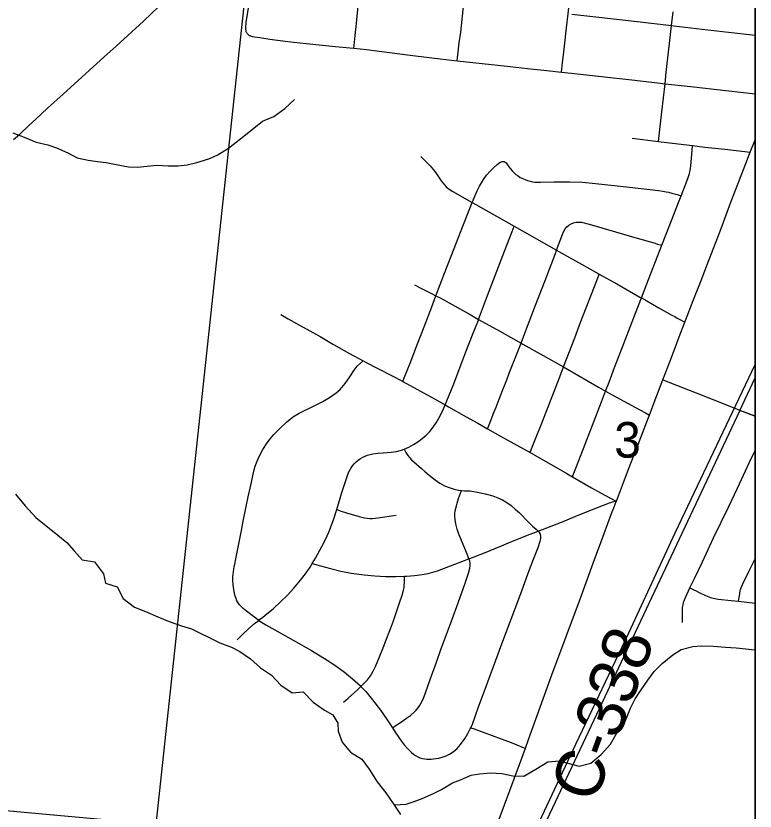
# Model space of a CAD drawing. Extents: x 0 to 1134, y 0 to 440.
# Drawn here: x 512.92 to 539, y 176.75 to 204.78 of the extents above; entities that cross this region are included whole.
import ezdxf

# ---------------------------------------------------------------- set-up
doc = ezdxf.new("R2010")
doc.units = 0
for name, color, linetype in [('Default', 7, 'Continuous'), ('GM_X_City_Street', 7, 'Continuous'), ('GM_X_County_Road', 7, 'Continuous'), ('GM_X_County_Road_Text', 7, 'Continuous'), ('GM_X_Minor_River', 7, 'Continuous'), ('GM_X_Rail_Line', 7, 'Continuous'), ('GM_X_Section', 7, 'Continuous'), ('GM_X_Section_Text', 7, 'Continuous'), ('GM_X_Township_Road', 7, 'Continuous'), ('GM_X_Unincorporated', 7, 'Continuous'), ('SH_Cut_Line', 7, 'Continuous'), ('SH_Text', 7, 'Continuous')]:
    doc.layers.add(name, color=color, linetype=linetype)

msp = doc.modelspace()

# ---------------------------------------------------------------- linework, layer by layer
at = {"layer": 'Default'}
msp.add_lwpolyline([(539, 174.139), (539, 205.4), (521.182, 207.228), (517.859, 176.283)], close=True, dxfattribs=at)
at = {"layer": 'GM_X_City_Street'}
for points in [[(521.083, 204.164), (521.072, 204.183), (521.062, 204.199), (521.051, 204.227), (521.042, 204.259), (521.037, 204.317), (521.036, 204.359), (521.05, 204.559), (521.091, 204.838), (521.19, 205.48), (521.245, 205.898), (521.274, 206.122), (521.291, 206.409), (521.321, 206.883), (521.352, 207.438), (521.393, 207.998), (521.403, 208.129), (521.401, 208.151), (521.398, 208.175), (521.391, 208.194), (521.379, 208.222), (521.333, 208.322)], [(532.166, 202.799), (532.18, 202.911), (532.21, 203.141), (532.233, 203.319), (532.277, 203.722), (532.347, 204.361), (532.404, 204.859), (532.454, 205.294), (532.528, 206.019), (532.576, 206.781), (532.617, 207.263), (532.654, 207.688), (532.685, 208.057), (532.724, 208.449)], [(524.844, 203.641), (524.855, 203.743), (524.892, 204.097), (524.926, 204.413), (524.949, 204.641), (524.976, 204.891), (525.024, 205.352), (525.06, 205.689), (525.091, 205.99), (525.14, 206.457), (525.204, 206.924), (525.257, 207.297), (525.309, 207.765), (525.328, 207.94)], [(528.49, 203.205), (528.562, 203.84), (528.614, 204.211), (528.721, 205.225), (528.728, 205.275), (528.746, 205.41), (528.766, 205.503), (528.825, 205.682), (528.863, 205.769), (528.996, 206.013), (529.034, 206.095), (529.064, 206.179), (529.088, 206.267), (529.106, 206.355), (529.127, 206.545), (529.145, 206.737), (529.164, 206.912), (529.187, 207.139), (529.218, 207.439), (529.233, 207.581)], [(535.595, 200.36), (535.619, 200.569), (535.715, 201.403), (535.822, 202.393), (535.866, 202.795), (535.985, 203.815), (536.054, 204.447), (536.107, 204.929)], [(532.54, 204.843), (533.276, 204.764), (534.842, 204.585), (536.054, 204.447), (536.132, 204.438), (537.333, 204.298), (539, 204.108)], [(521.083, 204.164), (521.102, 204.143), (521.128, 204.118), (521.156, 204.098), (521.176, 204.089), (521.195, 204.082), (521.261, 204.063), (521.341, 204.046), (521.531, 204.017), (521.887, 203.964), (522.522, 203.885), (523.166, 203.808), (524.199, 203.705), (524.708, 203.655), (524.844, 203.641), (525.297, 203.594), (526.732, 203.416), (527.593, 203.31), (528.087, 203.249), (528.49, 203.205), (529.046, 203.143), (530.248, 203.008), (531.081, 202.916), (531.544, 202.867), (532.166, 202.799), (532.738, 202.737), (533.58, 202.643), (534.647, 202.525), (535.556, 202.424), (535.822, 202.393), (536.729, 202.29), (537.557, 202.196), (539, 202.032)], [(534.663, 200.474), (535.595, 200.36), (535.887, 200.325), (536.795, 200.214), (537.222, 200.162), (537.927, 200.081), (538.637, 200), (538.829, 199.978)], [(532.556, 188.537), (532.607, 188.664), (532.676, 188.837), (532.945, 189.531), (533.577, 191.18), (533.725, 191.558), (533.847, 191.873), (534.044, 192.394), (534.306, 193.08), (534.776, 194.305), (534.987, 194.839), (535.186, 195.341), (535.714, 196.698), (535.995, 197.42), (536.295, 198.202), (536.396, 198.442), (536.537, 198.8), (536.631, 199.054), (536.683, 199.229), (536.72, 199.409), (536.731, 199.499), (536.753, 199.766), (536.779, 200.039), (536.795, 200.214)], [(526.57, 191.901), (526.62, 192.026), (526.827, 192.537), (527.096, 193.222), (527.329, 193.827), (527.593, 194.522), (527.742, 194.913), (528.048, 195.717), (528.282, 196.31), (528.712, 197.434), (529.018, 198.206), (529.088, 198.37), (529.195, 198.622), (529.278, 198.785), (529.418, 199.018), (529.525, 199.164), (529.644, 199.301), (529.773, 199.43), (529.884, 199.529), (529.96, 199.591), (530.005, 199.623), (530.044, 199.645), (530.083, 199.654)], [(527.203, 199.824), (527.456, 199.582), (527.538, 199.499), (527.657, 199.356), (527.714, 199.281), (527.921, 198.969), (528.039, 198.824), (528.105, 198.758), (528.176, 198.698), (528.332, 198.594), (529.018, 198.206), (529.146, 198.133), (529.881, 197.722), (530.501, 197.371), (531.999, 196.523), (532.079, 196.478), (533.464, 195.697), (533.504, 195.674), (534.118, 195.333), (534.93, 194.871), (534.987, 194.839), (535.177, 194.734), (535.58, 194.499), (536.062, 194.236), (536.164, 194.181), (536.255, 194.132), (536.346, 194.082), (536.525, 193.984)], [(530.083, 199.654), (530.114, 199.653), (530.15, 199.646), (530.18, 199.632), (530.214, 199.6), (530.267, 199.529), (530.314, 199.467), (530.43, 199.322), (530.495, 199.256), (530.565, 199.195), (530.639, 199.14), (530.718, 199.092), (530.885, 199.011), (530.973, 198.98), (531.062, 198.956), (531.153, 198.939), (531.245, 198.928), (531.431, 198.923), (531.894, 198.936), (532.45, 198.94), (532.913, 198.92), (533.375, 198.879), (534.573, 198.745), (535.587, 198.63), (535.744, 198.609), (535.861, 198.585), (535.946, 198.567), (536.057, 198.539), (536.246, 198.485), (536.396, 198.442)], [(528.067, 191.071), (528.125, 191.214), (528.369, 191.815), (528.593, 192.415), (528.688, 192.661), (528.795, 192.94), (529.034, 193.543), (529.238, 194.061), (529.247, 194.084), (529.564, 194.93), (530.162, 196.493), (530.428, 197.182), (530.501, 197.371)], [(529.564, 190.231), (529.616, 190.364), (529.788, 190.806), (529.861, 190.992), (529.969, 191.27), (530.089, 191.575), (530.238, 191.957), (530.328, 192.189), (530.743, 193.252), (530.803, 193.407), (531.258, 194.588), (531.589, 195.458), (531.957, 196.413), (531.999, 196.523), (532.22, 197.111), (532.258, 197.196), (532.303, 197.277), (532.361, 197.349), (532.432, 197.409), (532.512, 197.457), (532.598, 197.493), (532.689, 197.512), (532.782, 197.518), (532.875, 197.509), (533.145, 197.437), (533.592, 197.308), (534.757, 196.975), (535.473, 196.767), (535.562, 196.741), (535.714, 196.698)], [(531.061, 189.387), (531.115, 189.522), (531.304, 189.991), (531.427, 190.309), (531.555, 190.64), (531.695, 191.002), (531.859, 191.422), (532.106, 192.06), (532.24, 192.408), (532.637, 193.434), (532.834, 193.955), (533.44, 195.51), (533.504, 195.674)], [(526.984, 195.307), (527.227, 195.172), (527.558, 195.006), (527.742, 194.913), (527.889, 194.839), (528.943, 194.253), (529.247, 194.084), (529.999, 193.664), (530.743, 193.252), (530.812, 193.213), (532.24, 192.408), (532.38, 192.329), (533.479, 191.697), (533.725, 191.558), (533.963, 191.423), (534.782, 190.976), (535.129, 190.786), (535.27, 190.709)], [(536.437, 183.395), (536.437, 183.579), (536.437, 183.665), (536.436, 183.751), (536.438, 183.838), (536.444, 183.928), (536.457, 184.02), (536.478, 184.11), (536.505, 184.199), (536.539, 184.286), (536.701, 184.627), (536.857, 184.956), (537.142, 185.54), (537.531, 186.381), (538.061, 187.465), (538.376, 188.132), (538.808, 189.054), (539, 189.458)], [(538.415, 184.146), (538.446, 184.335), (538.475, 184.51), (538.49, 184.566), (538.507, 184.617), (538.53, 184.678), (538.577, 184.781), (538.776, 185.198), (539, 185.645)], [(536.701, 184.627), (536.842, 184.556), (536.923, 184.516), (537.005, 184.473), (537.254, 184.349), (537.427, 184.282), (537.516, 184.256), (537.697, 184.221), (538.157, 184.176), (538.415, 184.146), (539, 184.08)]]:
    msp.add_lwpolyline(points, dxfattribs=at)
at = {"layer": 'GM_X_County_Road'}
for p, q in [((538.829, 199.978), (539, 200.417)), ((538.546, 190.854), (539, 190.677)), ((534.017, 187.443), (534.052, 187.53))]:
    msp.add_line(p, q, dxfattribs=at)
for points in [[(512.836, 200.424), (513.046, 200.607), (513.381, 200.924), (513.626, 201.149), (514.039, 201.527), (514.595, 202.025), (516.043, 203.341), (516.459, 203.715), (517.426, 204.595), (517.965, 205.112), (518.509, 205.624), (518.95, 206.036)], [(536.525, 193.984), (536.55, 194.05), (536.82, 194.752), (537.093, 195.46), (537.356, 196.136), (537.626, 196.828), (537.804, 197.287), (538.148, 198.221), (538.673, 199.579), (538.829, 199.978)], [(535.747, 191.951), (535.987, 192.594), (536.154, 193.023), (536.326, 193.467), (536.525, 193.984)], [(535.27, 190.709), (535.478, 191.251), (535.747, 191.951)], [(535.747, 191.951), (536.92, 191.498), (538.047, 191.049), (538.546, 190.854)], [(534.106, 187.671), (534.433, 188.526), (534.562, 188.861), (534.702, 189.227), (534.838, 189.581), (534.967, 189.916), (535.237, 190.621), (535.27, 190.709)], [(534.052, 187.53), (534.079, 187.601), (534.106, 187.671)], [(530.895, 178.971), (531.003, 179.27), (531.421, 180.409), (531.835, 181.55), (532.84, 184.262), (533.288, 185.49), (533.678, 186.539), (533.935, 187.241), (534.017, 187.443)], [(529.505, 175.252), (529.739, 175.858), (529.974, 176.467), (530.685, 178.393), (530.895, 178.971)]]:
    msp.add_lwpolyline(points, dxfattribs=at)
at = {"layer": 'GM_X_Minor_River'}
for points in [[(512.814, 200.664), (513.221, 200.514), (513.64, 200.328), (514.048, 200.234), (514.353, 200.13), (514.76, 199.956), (515.088, 199.783), (515.473, 199.701), (515.802, 199.653), (516.108, 199.616), (516.46, 199.545), (516.89, 199.463), (517.208, 199.449), (517.549, 199.492), (517.89, 199.524), (518.298, 199.498), (518.65, 199.495), (518.968, 199.538), (519.309, 199.615), (519.73, 199.749), (520.026, 199.872), (520.425, 200.119), (520.859, 200.457), (521.258, 200.784), (521.624, 201.077), (522.022, 201.233), (522.41, 201.515), (522.753, 201.842)], [(512.911, 187.924), (513.249, 187.512), (513.631, 187.1), (514.398, 186.48), (514.726, 186.216), (514.984, 185.93), (515.266, 185.609), (515.697, 185.538), (516.011, 185.115), (516.088, 184.784), (516.496, 184.656), (516.708, 184.245), (517.103, 183.935), (517.499, 183.784), (517.929, 183.599), (518.336, 183.437), (518.767, 183.286), (519.117, 183.17), (519.423, 183.019), (519.739, 182.869), (520.112, 182.685), (520.531, 182.534), (520.825, 182.372), (521.198, 182.119), (521.547, 181.798), (521.942, 181.545), (522.269, 181.19), (522.664, 180.925), (523.062, 180.957), (523.411, 180.59), (523.806, 180.303), (524.1, 180.141), (524.279, 179.856), (524.288, 179.571), (524.433, 179.183), (524.725, 178.829), (525.121, 178.587), (525.39, 178.232), (525.671, 177.787), (525.974, 177.398), (526.232, 177.02), (526.491, 176.632)], [(526.267, 176.968), (526.686, 176.994), (526.971, 177.083), (527.255, 177.195), (527.654, 177.374), (527.938, 177.508), (528.326, 177.744), (528.611, 177.856), (528.986, 178.012), (529.282, 178.067), (529.668, 178.098), (530.065, 178.072), (530.45, 177.99), (530.847, 177.976), (531.269, 178.223), (531.691, 178.492), (532.1, 178.524), (532.394, 178.442), (532.791, 178.336), (533.2, 178.436), (533.565, 178.74), (533.897, 179.113), (534.15, 179.543), (534.437, 179.973), (534.61, 180.381), (534.772, 180.71), (534.978, 181.027), (535.219, 181.366), (535.437, 181.672), (535.723, 181.954), (536.1, 182.258), (536.396, 182.449), (536.805, 182.549), (537.101, 182.581), (537.532, 182.566), (537.952, 182.529), (538.326, 182.503), (538.677, 182.466), (538.995, 182.441), (539, 182.44)]]:
    msp.add_lwpolyline(points, dxfattribs=at)
at = {"layer": 'GM_X_Rail_Line'}
for p, q in [((538.46, 190.872), (539, 192.029)), ((539, 190.675), (538.46, 190.872))]:
    msp.add_line(p, q, dxfattribs=at)
for points in [[(523.793, 152.748), (524.72, 156.111), (526.82, 163.501), (529.132, 171.547), (530.926, 175.384), (532.671, 179.109), (534.549, 183.03), (536.181, 186.563), (539, 192.493)], [(538.46, 190.872), (531.264, 175.625), (529.455, 171.744), (523.761, 151.987), (521.638, 146.912), (519.773, 143.896), (517.683, 141.431), (515.36, 138.979), (514.776, 138.349), (513.736, 135.72), (513.018, 133.756), (510.064, 126.441), (504.279, 111.389), (503.424, 109.358), (496.783, 96.163), (485.546, 73.661), (478.157, 58.904), (470.789, 44.152), (463.212, 28.991)]]:
    msp.add_lwpolyline(points, dxfattribs=at)
at = {"layer": 'GM_X_Section'}
msp.add_lwpolyline([(490.882, 209.496), (521.182, 207.228), (517.859, 176.283), (488.076, 178.987)], close=True, dxfattribs=at)
at = {"layer": 'GM_X_Township_Road'}
for points in [[(522.267, 194.257), (522.524, 194.109), (522.924, 193.878), (523.656, 193.483), (524.133, 193.204), (524.695, 192.885), (525.175, 192.624)], [(521.488, 183.475), (521.462, 183.493), (521.385, 183.551), (521.305, 183.611), (521.061, 183.799), (520.945, 183.897), (520.874, 183.959), (520.812, 184.027), (520.762, 184.098), (520.721, 184.164), (520.69, 184.242), (520.659, 184.329), (520.636, 184.439), (520.611, 184.567), (520.593, 184.726), (520.577, 184.887), (520.579, 185.004), (520.584, 185.096), (520.595, 185.189), (520.622, 185.372), (520.641, 185.46), (520.677, 185.643), (520.879, 186.647), (520.945, 186.973), (521.037, 187.431), (521.118, 187.832), (521.217, 188.286), (521.255, 188.466), (521.316, 188.735), (521.367, 188.914), (521.431, 189.088), (521.507, 189.256), (521.64, 189.501), (521.79, 189.737), (521.901, 189.887), (522.02, 190.031), (522.22, 190.232), (522.466, 190.465), (522.594, 190.569), (522.715, 190.657), (522.777, 190.697), (522.914, 190.775), (523.417, 191.02), (523.75, 191.189), (523.99, 191.333), (524.218, 191.496), (524.36, 191.617), (524.425, 191.683), (524.543, 191.828), (524.698, 192.061), (524.851, 192.296), (524.968, 192.44), (525.175, 192.624)], [(525.175, 192.624), (525.579, 192.409), (526.317, 192.04), (526.57, 191.901)], [(526.57, 191.901), (527.695, 191.28), (528.067, 191.071)], [(526.615, 189.511), (526.782, 189.584), (526.946, 189.675), (527.104, 189.774), (527.258, 189.881), (527.399, 190.001), (527.529, 190.136), (527.645, 190.281), (527.747, 190.438), (527.885, 190.686), (528.012, 190.934), (528.067, 191.071)], [(528.067, 191.071), (528.179, 191.008), (528.813, 190.651), (529.214, 190.431), (529.564, 190.231)], [(529.564, 190.231), (530.017, 189.971), (531.061, 189.387)], [(524.242, 187.378), (524.419, 187.98), (524.536, 188.335), (524.618, 188.587), (524.66, 188.686), (524.699, 188.77), (524.746, 188.851), (524.8, 188.927), (524.861, 188.998), (524.928, 189.063), (525, 189.122), (525.076, 189.176), (525.157, 189.223), (525.241, 189.263), (525.328, 189.297), (525.418, 189.325), (525.509, 189.345), (525.694, 189.366), (525.881, 189.382), (526.16, 189.407), (526.345, 189.43), (526.436, 189.448), (526.526, 189.472), (526.615, 189.511)], [(526.615, 189.511), (526.675, 189.395), (526.744, 189.287), (526.807, 189.214), (526.88, 189.136), (527.23, 188.827), (527.364, 188.714), (527.506, 188.596), (527.717, 188.429), (527.877, 188.311), (527.956, 188.263), (528.038, 188.221), (528.21, 188.154), (528.387, 188.098), (528.534, 188.064), (528.64, 188.049)], [(531.061, 189.387), (531.228, 189.293), (532.358, 188.652), (532.556, 188.537)], [(532.556, 188.537), (533.229, 188.15), (533.564, 187.958), (534.027, 187.714), (534.106, 187.671)], [(528.907, 185.64), (528.867, 185.755), (528.797, 185.922), (528.765, 186.009), (528.62, 186.347), (528.553, 186.519), (528.495, 186.695), (528.447, 186.875), (528.415, 187.033), (528.408, 187.151), (528.409, 187.24), (528.422, 187.332), (528.462, 187.513), (528.485, 187.601), (528.541, 187.774), (528.572, 187.86), (528.64, 188.049)], [(528.64, 188.049), (528.659, 188.047), (528.75, 188.044), (528.934, 188.035), (529.208, 187.999), (529.48, 187.94), (529.746, 187.862), (529.919, 187.798), (530.087, 187.721), (530.247, 187.627), (530.397, 187.518), (530.538, 187.399), (530.673, 187.272), (531.003, 186.942), (531.151, 186.794), (531.271, 186.689), (531.353, 186.622)], [(531.353, 186.622), (531.81, 186.801), (532.226, 186.964), (532.822, 187.203), (533.439, 187.452), (533.859, 187.615), (533.913, 187.634), (533.974, 187.651), (534.019, 187.66), (534.106, 187.671)], [(523.38, 185.481), (523.493, 185.667), (523.718, 186.076), (523.844, 186.327), (523.958, 186.582), (524.125, 187.015), (524.242, 187.378)], [(524.242, 187.378), (524.396, 187.329), (524.586, 187.269), (525.037, 187.133), (525.22, 187.089), (525.313, 187.074), (525.406, 187.066), (525.5, 187.065), (525.688, 187.085), (526.34, 187.187)], [(528.907, 185.64), (528.934, 185.65), (529.451, 185.857), (530.051, 186.106), (530.306, 186.209), (531.035, 186.5), (531.199, 186.561), (531.353, 186.622)], [(528.97, 179.69), (529.025, 179.819), (529.244, 180.431), (529.371, 180.761), (529.851, 182.07), (530.067, 182.643), (530.23, 183.076), (530.523, 183.855), (530.782, 184.548), (531.028, 185.235), (531.18, 185.63), (531.346, 186.048), (531.422, 186.262), (531.442, 186.366), (531.442, 186.427), (531.427, 186.513), (531.398, 186.568), (531.353, 186.622)], [(526.21, 179.683), (526.342, 179.775), (526.492, 179.879), (526.698, 180.022), (526.844, 180.124), (526.985, 180.245), (527.048, 180.312), (527.107, 180.384), (527.16, 180.461), (527.207, 180.54), (527.285, 180.702), (527.388, 180.958), (527.541, 181.395), (527.757, 182.006), (527.914, 182.442), (528.041, 182.789), (528.297, 183.484), (528.521, 184.092), (528.773, 184.789), (528.892, 185.14), (528.94, 185.32), (528.953, 185.411), (528.948, 185.485), (528.931, 185.572), (528.907, 185.64)], [(526.634, 185.029), (526.703, 185.031), (526.982, 185.053), (527.26, 185.089), (527.471, 185.129), (527.634, 185.168), (527.801, 185.223), (528.411, 185.454), (528.907, 185.64)], [(521.488, 183.475), (521.521, 183.502), (521.633, 183.588), (521.781, 183.703), (521.996, 183.881), (522.26, 184.123), (522.502, 184.357), (522.73, 184.607), (522.968, 184.89), (523.139, 185.114), (523.299, 185.347), (523.38, 185.481)], [(523.38, 185.481), (523.664, 185.4), (524.022, 185.299), (524.385, 185.214), (524.751, 185.144), (525.214, 185.08), (525.585, 185.043), (525.957, 185.022), (526.33, 185.019), (526.634, 185.029)], [(525.097, 181.148), (525.222, 181.276), (525.325, 181.38), (525.431, 181.522), (525.526, 181.68), (525.609, 181.846), (525.755, 182.186), (525.902, 182.564), (525.963, 182.727), (526.134, 183.175), (526.244, 183.462), (526.401, 183.921), (526.459, 184.097), (526.549, 184.36), (526.598, 184.538), (526.615, 184.628), (526.625, 184.719), (526.627, 184.804), (526.634, 185.029)], [(520.733, 182.791), (520.927, 182.991), (521.141, 183.186), (521.343, 183.359), (521.488, 183.475)], [(521.488, 183.475), (521.741, 183.322), (522.059, 183.141), (523.352, 182.417), (523.906, 182.076), (524.214, 181.87), (524.512, 181.648), (524.801, 181.414), (525.078, 181.167), (525.097, 181.148)], [(524.484, 180.588), (524.641, 180.731), (524.97, 181.029), (525.097, 181.148)], [(525.097, 181.148), (525.178, 181.063), (525.271, 180.966), (525.504, 180.677), (525.785, 180.308), (525.999, 180.004), (526.21, 179.683)], [(526.21, 179.683), (526.305, 179.538), (526.513, 179.23), (526.626, 179.082), (526.748, 178.942), (526.882, 178.815), (526.954, 178.759), (527.024, 178.709), (527.097, 178.665), (527.178, 178.631), (527.268, 178.604), (527.344, 178.589), (527.425, 178.585), (527.568, 178.585), (527.736, 178.6), (527.845, 178.614), (527.963, 178.649), (528.1, 178.703), (528.224, 178.763), (528.349, 178.843), (528.421, 178.898), (528.488, 178.96), (528.608, 179.101), (528.771, 179.327), (528.868, 179.485), (528.952, 179.649), (528.97, 179.69)], [(528.97, 179.69), (529.093, 179.645), (530.037, 179.299), (530.393, 179.163), (530.599, 179.084), (530.823, 178.998), (530.895, 178.971)]]:
    msp.add_lwpolyline(points, dxfattribs=at)
at = {"layer": 'GM_X_Unincorporated'}
msp.add_lwpolyline([(539, 113.439), (539, 295.833)], dxfattribs=at)
at = {"layer": 'SH_Cut_Line'}
msp.add_lwpolyline([(539, 17.107), (539, 425.107), (205.806, 425.107)], dxfattribs=at)
at = {"layer": 'SH_Text'}
msp.add_lwpolyline([(131, 425.107), (539, 425.107), (539, 17.107), (131, 17.107)], close=True, dxfattribs=at)

# ---------------------------------------------------------------- texts
at = {"layer": 'GM_X_County_Road_Text'}
msp.add_text('C-338', height=1.7045, rotation=69.9238, dxfattribs=at).set_placement((533.341, 176.977))
at = {"layer": 'GM_X_Section_Text'}
msp.add_text('3', height=1.256, rotation=0, dxfattribs=at).set_placement((534.031, 189.211))

doc.saveas('drawing.dxf')
